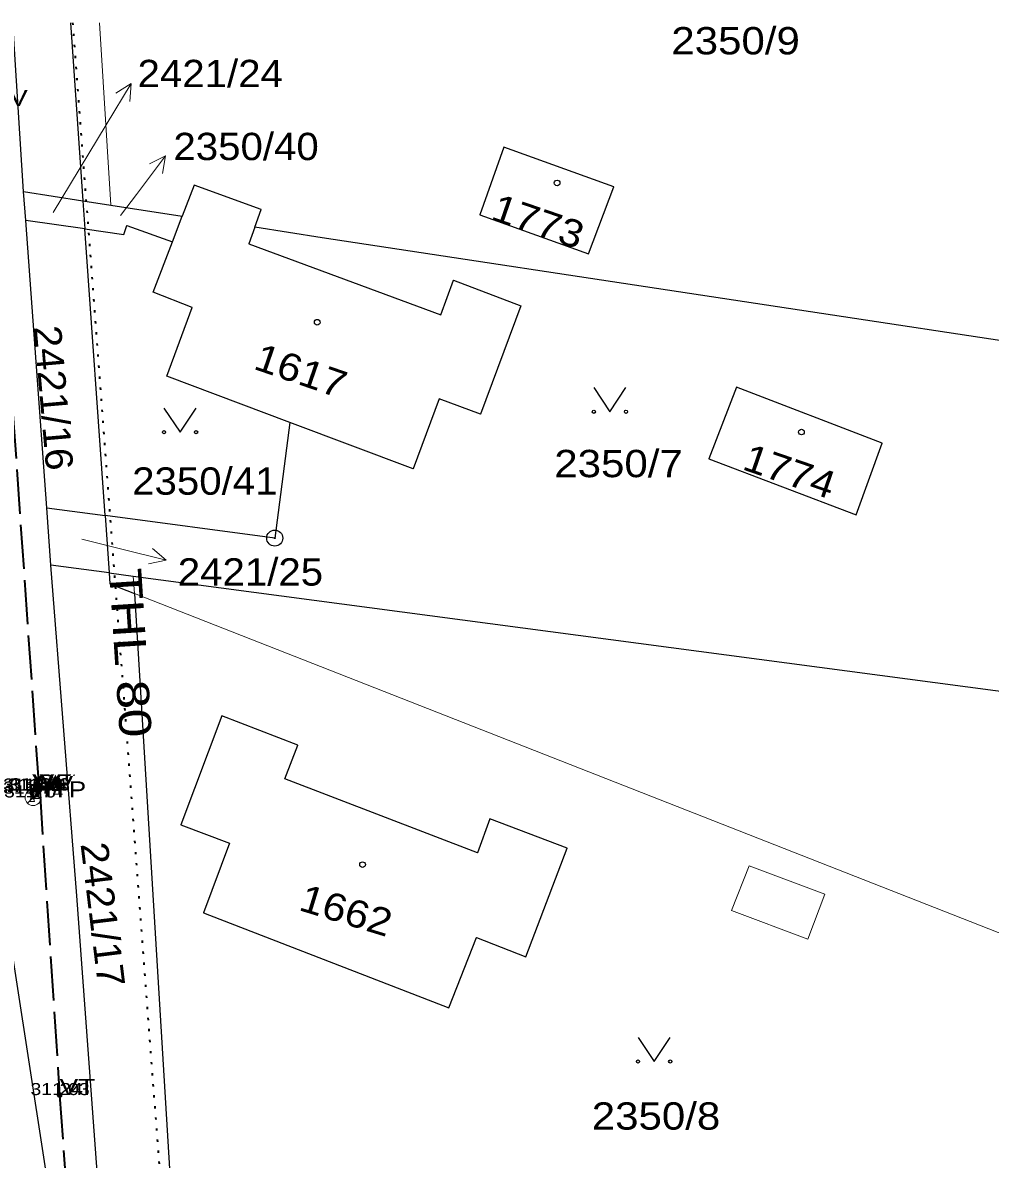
# Model space of a CAD drawing. Extents: x -652394 to -652006, y -1024262 to -1023975.
# Drawn here: x -652323 to -652262.8, y -1024046.7 to -1023975.9 of the extents above; entities that cross this region are included whole.
import ezdxf
from ezdxf.enums import TextEntityAlignment as Align

# ---------------------------------------------------------------- set-up
doc = ezdxf.new("R2010")
doc.units = 0
doc.header["$LTSCALE"] = 0.46
doc.header["$PDMODE"] = 32
doc.header["$PDSIZE"] = 0.23
doc.linetypes.add('DOTTED', pattern=[1.5, 0.3, -1.2])
doc.linetypes.add('LONG_DASHED', pattern=[7.5, 6, -1.5])
for name, color, linetype in [('1', 7, 'Continuous'), ('17', 7, 'Continuous'), ('2', 7, 'Continuous'), ('3', 7, 'Continuous'), ('4', 7, 'Continuous')]:
    doc.layers.add(name, color=color, linetype=linetype)
for name, color, linetype, lineweight in [('10', 7, 'Continuous', 13), ('12', 7, 'Continuous', 13), ('35', 7, 'LONG_DASHED', 35), ('36', 7, 'DOTTED', 35), ('63', 7, 'Continuous', 25)]:
    doc.layers.add(name, color=color, linetype=linetype, lineweight=lineweight)

msp = doc.modelspace()

# ---------------------------------------------------------------- linework, layer by layer
at = {"layer": '1'}
for p in [(-652322.39, -1024023.72), (-652322.11, -1024023.72), (-652321.94, -1024023.7), (-652321.921, -1024023.709), (-652322.39, -1024023.91), (-652322.33, -1024024.15), (-652320.684, -1024042.669)]:
    msp.add_point(p, dxfattribs=at)
at = {"layer": '10'}
for p, q in [((-652322.68, -1024023.35), (-652321.98, -1024023.35)), ((-652322.33, -1024023.65), (-652322.33, -1024023.35)), ((-652322.684, -1024024.504), (-652321.977, -1024023.797))]:
    msp.add_line(p, q, dxfattribs=at)
for points in [[(-652322.24, -1024024.41), (-652322.54, -1024023.41), (-652322.24, -1024023.41), (-652322.54, -1024024.41)], [(-652321.96, -1024024.22), (-652322.26, -1024023.22), (-652321.96, -1024023.22), (-652322.26, -1024024.22)]]:
    msp.add_lwpolyline(points, close=True, dxfattribs=at)
msp.add_circle((-652322.329, -1024024.15), 0.5, dxfattribs=at)
at = {"layer": '12'}
for centre, radius in [((-652322.39, -1024023.72), 0.15), ((-652321.94, -1024023.7), 0.15), ((-652322.39, -1024023.72), 0.075), ((-652321.94, -1024023.7), 0.075), ((-652320.684, -1024042.669), 0.15), ((-652320.684, -1024042.669), 0.075)]:
    msp.add_circle(centre, radius, dxfattribs=at)
at = {"layer": '35'}
for p, q in [((-652322.11, -1024023.72), (-652322.39, -1024023.72)), ((-652322.39, -1024023.91), (-652322.39, -1024023.72)), ((-652322.33, -1024024.15), (-652322.39, -1024023.91)), ((-652321.94, -1024023.7), (-652322.11, -1024023.72)), ((-652321.921, -1024023.709), (-652320.684, -1024042.669)), ((-652320.684, -1024042.669), (-652319.636, -1024057.436))]:
    msp.add_line(p, q, dxfattribs=at)
msp.add_lwpolyline([(-652321.94, -1024023.7), (-652324.89, -1023981.08), (-652325.2, -1023976.32)], dxfattribs=at)
at = {"layer": '36'}
msp.add_line((-652319.873, -1023975.941), (-652312.299, -1024075.98), dxfattribs=at)
msp.add_lwpolyline([(-652390.132, -1024015.68), (-652338.593, -1024023.847), (-652322.39, -1024023.72)], dxfattribs=at)
at = {"layer": '63'}
for p, q in [((-652322.92, -1023986.45), (-652323.6, -1023975.941)), ((-652320.01, -1023975.941), (-652319.23, -1023987.02)), ((-652319.23, -1023987.02), (-652319.11, -1023988.77)), ((-652319.11, -1023988.77), (-652322.79, -1023988.24)), ((-652313.66, -1023989.57), (-652313.05, -1023987.97)), ((-652319.11, -1023988.77), (-652316.69, -1023989.12)), ((-652317.85, -1024006.6), (-652319.11, -1023988.77)), ((-652316.69, -1023989.12), (-652316.49, -1023988.56)), ((-652316.49, -1023988.56), (-652313.66, -1023989.57)), ((-652308.54, -1023988.67), (-652308.92, -1023989.69)), ((-652314.87, -1023992.71), (-652313.66, -1023989.57)), ((-652321.48, -1024006.12), (-652317.85, -1024006.6)), ((-652321.22, -1024009.69), (-652321.48, -1024006.12)), ((-652317.85, -1024006.6), (-652317.6, -1024010.17)), ((-652317.6, -1024010.17), (-652321.22, -1024009.69))]:
    msp.add_line(p, q, dxfattribs=at)
at = {"layer": '63', "lineweight": 13}
for p, q in [((-652318.19, -1023975.941), (-652317.5, -1023987.29)), ((-652316.234, -1023979.728), (-652317.179, -1023980.328)), ((-652321.09, -1023987.75), (-652317.78, -1023982.3)), ((-652314.084, -1023984.223), (-652315.087, -1023984.722)), ((-652316.9, -1023987.94), (-652315.89, -1023986.62)), ((-652319.3, -1024008.08), (-652316.97, -1024008.65)), ((-652314.058, -1024009.376), (-652314.909, -1024008.648)), ((-652316.1, -1024010.37), (-652316.03, -1024011.45)), ((-652316.03, -1024011.45), (-652252.69, -1024036.32))]:
    msp.add_line(p, q, dxfattribs=at)
for points in [[(-652317.78, -1023982.3), (-652316.234, -1023979.728), (-652316.321, -1023980.844)], [(-652315.89, -1023986.62), (-652314.084, -1023984.223), (-652314.287, -1023985.324)], [(-652316.97, -1024008.65), (-652314.058, -1024009.376), (-652315.151, -1024009.62)], [(-652278.89, -1024031.19), (-652277.78, -1024028.41), (-652273.08, -1024030.17)], [(-652278.89, -1024031.19), (-652274.13, -1024032.97), (-652273.08, -1024030.17)]]:
    msp.add_lwpolyline(points, dxfattribs=at)
at = {"layer": '63'}
for points in [[(-652286.2, -1023986.15), (-652293.04, -1023983.69), (-652294.55, -1023987.89), (-652287.78, -1023990.33)], [(-652269.52, -1024002.11), (-652278.57, -1023998.62), (-652280.29, -1024003.08), (-652271.14, -1024006.57)], [(-652289.11, -1024027.31), (-652293.91, -1024025.48), (-652294.68, -1024027.6), (-652306.67, -1024022.99), (-652305.87, -1024020.9), (-652310.6, -1024019.08), (-652313.15, -1024025.85), (-652310.11, -1024027), (-652311.74, -1024031.32), (-652296.47, -1024037.23), (-652294.74, -1024032.86), (-652291.68, -1024034.06)]]:
    msp.add_lwpolyline(points, close=True, dxfattribs=at)
at = {"layer": '63', "lineweight": 13}
for points in [[(-652286.2, -1023986.15), (-652293.04, -1023983.69), (-652294.55, -1023987.89), (-652287.78, -1023990.33)], [(-652294.55, -1023987.89), (-652287.78, -1023990.33), (-652286.2, -1023986.15), (-652293.04, -1023983.69)], [(-652313.05, -1023987.97), (-652313.66, -1023989.57), (-652314.87, -1023992.71), (-652312.44, -1023993.67), (-652314.01, -1023997.93), (-652306.35, -1024000.82), (-652298.69, -1024003.7), (-652297.07, -1023999.34), (-652294.51, -1024000.29), (-652292, -1023993.55), (-652296.17, -1023991.97), (-652296.96, -1023994.12), (-652308.92, -1023989.69), (-652308.54, -1023988.67), (-652308.14, -1023987.57), (-652312.31, -1023986.04)], [(-652296.17, -1023991.97), (-652296.96, -1023994.12), (-652308.92, -1023989.69), (-652308.54, -1023988.67), (-652308.14, -1023987.57), (-652312.31, -1023986.04), (-652313.05, -1023987.97), (-652313.66, -1023989.57), (-652314.87, -1023992.71), (-652312.44, -1023993.67), (-652314.01, -1023997.93), (-652306.35, -1024000.82), (-652298.69, -1024003.7), (-652297.07, -1023999.34), (-652294.51, -1024000.29), (-652292, -1023993.55)], [(-652322.92, -1023986.45), (-652322.79, -1023988.24), (-652319.11, -1023988.77), (-652319.23, -1023987.02)], [(-652316.69, -1023989.12), (-652316.49, -1023988.56), (-652313.66, -1023989.57), (-652313.05, -1023987.97), (-652317.5, -1023987.29), (-652319.23, -1023987.02), (-652319.11, -1023988.77)], [(-652317.85, -1024006.6), (-652319.11, -1023988.77), (-652322.79, -1023988.24), (-652321.48, -1024006.12)], [(-652306.35, -1024000.82), (-652314.01, -1023997.93), (-652312.44, -1023993.67), (-652314.87, -1023992.71), (-652313.66, -1023989.57), (-652316.49, -1023988.56), (-652316.69, -1023989.12), (-652319.11, -1023988.77), (-652317.85, -1024006.6), (-652307.3, -1024008.01)], [(-652304.35, -1023989.32), (-652308.54, -1023988.67), (-652308.92, -1023989.69), (-652296.96, -1023994.12), (-652296.17, -1023991.97), (-652292, -1023993.55), (-652294.51, -1024000.29), (-652297.07, -1023999.34), (-652298.69, -1024003.7), (-652306.35, -1024000.82), (-652307.3, -1024008.01), (-652317.85, -1024006.6), (-652317.6, -1024010.17), (-652316.1, -1024010.37), (-652254.95, -1024018.48), (-652253.52, -1024018.67), (-652254.55, -1023996.87)], [(-652269.52, -1024002.11), (-652278.57, -1023998.62), (-652280.29, -1024003.08), (-652271.14, -1024006.57)], [(-652269.52, -1024002.11), (-652271.14, -1024006.57), (-652280.29, -1024003.08), (-652278.57, -1023998.62)], [(-652278.57, -1023998.62), (-652280.29, -1024003.08), (-652271.14, -1024006.57), (-652269.52, -1024002.11)], [(-652321.48, -1024006.12), (-652321.22, -1024009.69), (-652317.6, -1024010.17), (-652317.85, -1024006.6)], [(-652317.6, -1024010.17), (-652321.22, -1024009.69), (-652319.61, -1024030.28), (-652317.98, -1024052.48), (-652313.5, -1024053.04), (-652316.03, -1024011.45), (-652317.55, -1024010.86)], [(-652308.71, -1024053.79), (-652308.31, -1024052.74), (-652303.5, -1024054.52), (-652286.04, -1024056.49), (-652251.57, -1024060.11), (-652252.69, -1024036.32), (-652253.52, -1024018.67), (-652254.95, -1024018.48), (-652316.1, -1024010.37), (-652317.6, -1024010.17), (-652317.55, -1024010.86), (-652316.03, -1024011.45), (-652313.5, -1024053.04)], [(-652289.11, -1024027.31), (-652291.68, -1024034.06), (-652294.74, -1024032.86), (-652296.47, -1024037.23), (-652311.74, -1024031.32), (-652310.11, -1024027), (-652313.15, -1024025.85), (-652310.6, -1024019.08), (-652305.87, -1024020.9), (-652306.67, -1024022.99), (-652294.68, -1024027.6), (-652293.91, -1024025.48)], [(-652289.11, -1024027.31), (-652293.91, -1024025.48), (-652294.68, -1024027.6), (-652306.67, -1024022.99), (-652305.87, -1024020.9), (-652310.6, -1024019.08), (-652313.15, -1024025.85), (-652310.11, -1024027), (-652311.74, -1024031.32), (-652296.47, -1024037.23), (-652294.74, -1024032.86), (-652291.68, -1024034.06)], [(-652313.15, -1024025.85), (-652310.11, -1024027), (-652311.74, -1024031.32), (-652296.47, -1024037.23), (-652294.74, -1024032.86), (-652291.68, -1024034.06), (-652289.11, -1024027.31), (-652293.91, -1024025.48), (-652294.68, -1024027.6), (-652306.67, -1024022.99), (-652305.87, -1024020.9), (-652310.6, -1024019.08)]]:
    msp.add_lwpolyline(points, close=True, dxfattribs=at)
at = {"layer": '63'}
for points in [[(-652308.54, -1023988.67), (-652308.14, -1023987.57), (-652312.31, -1023986.04), (-652313.05, -1023987.97)], [(-652321.48, -1024006.12), (-652322.79, -1023988.24), (-652322.92, -1023986.45), (-652319.23, -1023987.02)], [(-652319.23, -1023987.02), (-652317.5, -1023987.29), (-652313.05, -1023987.97)], [(-652254.55, -1023996.87), (-652304.35, -1023989.32), (-652308.54, -1023988.67)], [(-652308.92, -1023989.69), (-652296.96, -1023994.12), (-652296.17, -1023991.97), (-652292, -1023993.55), (-652294.51, -1024000.29), (-652297.07, -1023999.34), (-652298.69, -1024003.7), (-652306.35, -1024000.82)], [(-652306.35, -1024000.82), (-652314.01, -1023997.93), (-652312.44, -1023993.67), (-652314.87, -1023992.71)], [(-652287.45, -1023998.649), (-652286.45, -1024000.15), (-652285.45, -1023998.649)], [(-652314.19, -1023999.919), (-652313.19, -1024001.42), (-652312.19, -1023999.919)], [(-652306.35, -1024000.82), (-652307.3, -1024008.01), (-652317.85, -1024006.6)], [(-652317.98, -1024052.48), (-652319.61, -1024030.28), (-652321.22, -1024009.69)], [(-652317.6, -1024010.17), (-652316.1, -1024010.37), (-652254.95, -1024018.48), (-652253.52, -1024018.67)], [(-652317.6, -1024010.17), (-652317.55, -1024010.86), (-652316.03, -1024011.45), (-652313.5, -1024053.04)], [(-652313.58, -1024101.21), (-652314.61, -1024096.94), (-652318.74, -1024074.97), (-652320.04, -1024057.03), (-652325.05, -1024024.73), (-652325.11, -1024024.18)], [(-652284.7, -1024039.079), (-652283.7, -1024040.58), (-652282.7, -1024039.079)]]:
    msp.add_lwpolyline(points, dxfattribs=at)
for centre, radius in [((-652289.7368, -1023985.9092), 0.175), ((-652304.6568, -1023994.5792), 0.175), ((-652287.45, -1024000.1495), 0.1), ((-652285.45, -1024000.1495), 0.1), ((-652314.19, -1024001.4195), 0.1), ((-652312.19, -1024001.4195), 0.1), ((-652274.5368, -1024001.4092), 0.175), ((-652307.3, -1024008.0099), 0.5), ((-652307.3, -1024008.0099), 0.0303), ((-652301.8368, -1024028.3292), 0.175), ((-652284.7, -1024040.5795), 0.1), ((-652282.7, -1024040.5795), 0.1)]:
    msp.add_circle(centre, radius, dxfattribs=at)

# ---------------------------------------------------------------- texts
at = {"layer": '17', "width": 1.2}
msp.add_text('THL 80', height=2, rotation=273.675, dxfattribs=at).set_placement((-652317.2684, -1024015.2204), align=Align.CENTER)
at = {"layer": '2', "width": 1.3}
for s, p in [('67', (-652322.39, -1024023.72)), ('70', (-652322.33, -1024024.15)), ('68', (-652322.11, -1024023.72)), ('66', (-652321.94, -1024023.7)), ('23', (-652321.921, -1024023.709)), ('24', (-652320.684, -1024042.669))]:
    msp.add_text(s, height=0.75, dxfattribs=at).set_placement(p)
at = {"layer": '3', "width": 1.2}
for s, p in [('311 74 ', (-652322.188, -1024023.72)), ('311 74 ', (-652322.188, -1024023.91)), ('311 74 ', (-652322.128, -1024024.15)), ('311 74 ', (-652321.908, -1024023.72)), ('311 76 ', (-652321.738, -1024023.7)), ('311 83 ', (-652321.719, -1024023.709)), ('311 03 ', (-652320.482, -1024042.669))]:
    msp.add_text(s, height=0.75, dxfattribs=at).set_placement(p, align=Align.CENTER)
at = {"layer": '4'}
for s, width, p in [('SV', 1.3, (-652324.98, -1023981.12)), ('V', 1.55, (-652322.39, -1024023.72)), ('SV', 1.3, (-652322.11, -1024023.72)), ('V', 1.55, (-652321.94, -1024023.7)), ('VT', 1.3, (-652321.921, -1024023.709)), ('HYP', 1.2, (-652322.33, -1024024.15)), ('VT', 1.3, (-652320.684, -1024042.669))]:
    msp.add_text(s, height=1, dxfattribs=dict(at, width=width)).set_placement(p)
at = {"layer": '63'}
for s, width, p in [('2350/9', 1.15, (-652282.63, -1023977.91)), ('2421/24', 1.1, (-652315.83, -1023979.95)), ('2350/40', 1.1, (-652313.6, -1023984.49)), ('2350/7', 1.15, (-652289.91, -1024004.22)), ('2350/41', 1.1, (-652316.168, -1024005.31)), ('2421/25', 1.1, (-652313.33, -1024010.966)), ('2350/8', 1.15, (-652287.58, -1024044.82))]:
    msp.add_text(s, height=1.7, dxfattribs=dict(at, width=width)).set_placement(p)
for s, rotation, width, p in [('1773', 341, 1.15, (-652293.937, -1023988.157)), ('2421/16', 275, 1.1, (-652322.296, -1023994.854)), ('1617', 341, 1.15, (-652308.697, -1023997.457)), ('1774', 341, 1.15, (-652278.297, -1024003.707)), ('2421/17', 277, 1.1, (-652319.383, -1024027.043)), ('1662', 343, 1.15, (-652305.886, -1024031.139))]:
    msp.add_text(s, height=1.7, rotation=rotation, dxfattribs=dict(at, width=width)).set_placement(p)

doc.saveas('drawing.dxf')
